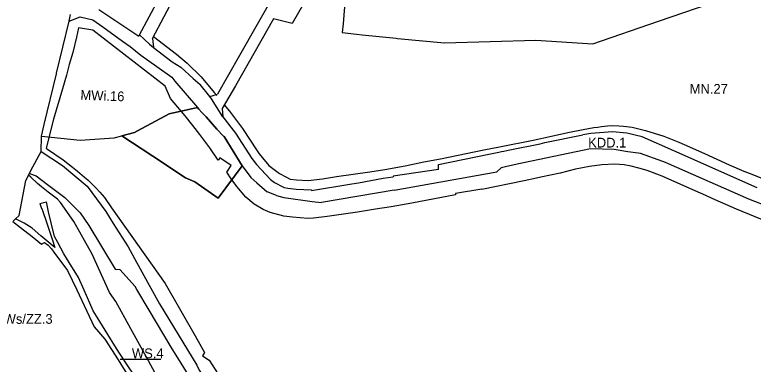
# Model space of a CAD drawing. Extents: x 7418991 to 7423142, y 5547704 to 5549547.
# Drawn here: x 7419654.4 to 7420035, y 5548816.8 to 5548996.8 of the extents above; entities that cross this region are included whole.
import ezdxf

# ---------------------------------------------------------------- set-up
doc = ezdxf.new("R2010")
doc.units = 0
for name, color, linetype in [('LIN_Linia Zabudowy Nieprzekraczalna', 7, 'Continuous'), ('LIN_linie_rozgraniczajace', 7, 'Continuous'), ('strefa_lokalizacji_usług', 7, 'Continuous'), ('TXT_Oznaczenia_przeznaczen', 7, 'Continuous')]:
    doc.layers.add(name, color=color, linetype=linetype)

msp = doc.modelspace()

# ---------------------------------------------------------------- linework, layer by layer
at = {"layer": 'LIN_Linia Zabudowy Nieprzekraczalna'}
for points in [[(7420045.62, 5548888.77), (7420026.39, 5548896.72), (7420015.43, 5548901.52), (7420008.94, 5548904.39), (7420003.92, 5548906.66), (7419988, 5548913.69), (7419980.27, 5548916.56), (7419976.07, 5548917.8), (7419972.03, 5548918.84), (7419968.54, 5548919.54), (7419963.69, 5548919.91), (7419956.87, 5548919.49), (7419950.58, 5548918.56), (7419943.4, 5548917.34), (7419935.48, 5548915.29), (7419925.44, 5548913.15), (7419923.24, 5548912.68), (7419916.91, 5548911.22), (7419895.09, 5548906.86), (7419895.06, 5548907.05), (7419881.49, 5548904.66), (7419881.58, 5548904.11), (7419859.09, 5548899.81), (7419848.41, 5548897.83), (7419840.39, 5548896.59), (7419830.96, 5548895.21), (7419815.4, 5548892.89), (7419808.38, 5548892), (7419805.4, 5548891.83), (7419797.49, 5548892.47), (7419793.15, 5548893.14), (7419786.02, 5548894.87), (7419782.45, 5548896.57), (7419777.79, 5548899.26), (7419773.51, 5548902.84), (7419768.81, 5548908.36), (7419766.01, 5548912.27), (7419763.62, 5548915.72), (7419765.86, 5548919.12), (7419760.14, 5548923.1), (7419759.33, 5548921.95), (7419759.29, 5548921.98), (7419754.95, 5548928.24), (7419749.76, 5548935.12), (7419746.24, 5548939.68), (7419742.23, 5548944.65), (7419734.66, 5548953.71), (7419731.95, 5548960.05), (7419694.59, 5548988.84), (7419687.31, 5548990.06), (7419686.16, 5548985.29), (7419684.29, 5548977.28), (7419682.52, 5548971.19), (7419681.01, 5548965.64), (7419679.03, 5548958.69), (7419674.4, 5548943.06), (7419670.62, 5548928.04), (7419670.7, 5548927.96), (7419671.2, 5548927.57), (7419679.33, 5548922.01), (7419684.19, 5548918.31), (7419686.79, 5548916.22), (7419690.4, 5548913.21), (7419691.98, 5548911.75), (7419693.63, 5548910.18), (7419695.35, 5548908.47), (7419696.33, 5548907.45), (7419698.16, 5548905.4), (7419700.63, 5548902.67), (7419704.33, 5548897.43), (7419731.96, 5548858.42), (7419747.34, 5548831.4), (7419752.24, 5548822.89), (7419751.11, 5548821.1), (7419754.53, 5548818.94), (7419759.18, 5548811.75)], [(7419725.91, 5548985.58), (7419737.67, 5548976.51), (7419743.17, 5548971.79)], [(7419743.17, 5548971.79), (7419750.43, 5548964.74), (7419757.23, 5548956.69), (7419758.46, 5548955.22)], [(7419762.4, 5548950.44), (7419765.06, 5548947.09), (7419771.7, 5548938.18), (7419779.3, 5548926.72), (7419780.44, 5548925.12), (7419785.42, 5548919.23), (7419790.8, 5548915.06), (7419794.11, 5548913.27), (7419796.36, 5548912.2), (7419799.55, 5548911.74), (7419805.62, 5548911.39), (7419813, 5548912.24), (7419820.13, 5548913.45)], [(7419873.78, 5548922.58), (7419896.06, 5548927.14), (7419904.24, 5548928.72), (7419921.52, 5548932.23), (7419931.02, 5548934.23), (7419939.39, 5548936.21), (7419947.36, 5548937.77), (7419952.81, 5548938.69), (7419954.96, 5548938.94), (7419956.77, 5548939.21), (7419959.8, 5548939.5), (7419962.45, 5548939.68), (7419965.76, 5548939.58), (7419968.18, 5548939.44), (7419972.58, 5548938.87), (7419979.54, 5548937.23), (7419988.95, 5548934.19), (7419996.58, 5548931.17), (7419999.41, 5548929.93), (7420009.83, 5548925.29), (7420016.16, 5548922.39), (7420022.61, 5548919.58)], [(7419820.13, 5548913.45), (7419837.44, 5548915.95), (7419845.12, 5548917.12), (7419855.52, 5548919.03), (7419865.27, 5548921), (7419873.78, 5548922.58)], [(7420022.61, 5548919.58), (7420030.2, 5548916.29), (7420032.93, 5548915.22), (7420038.5, 5548912.93), (7420052.44, 5548907.31), (7420057.96, 5548905.38), (7420062.32, 5548904.19), (7420064.15, 5548903.97), (7420069.56, 5548904.31), (7420075.9, 5548905.75), (7420086.49, 5548909.16)]]:
    msp.add_lwpolyline(points, dxfattribs=at)
at = {"layer": 'LIN_linie_rozgraniczajace'}
for p, q in [((7419725.38, 5548984.58), (7419725.97, 5548979.97)), ((7419735.52, 5548972.51), (7419739.93, 5548969.85)), ((7419739.93, 5548969.85), (7419746.39, 5548964.02)), ((7419746.39, 5548964.02), (7419749.9, 5548960.84)), ((7419754.93, 5548954.62), (7419758.81, 5548955.82)), ((7419990.6, 5548920.38), (7419991.12, 5548920.19)), ((7419991.12, 5548920.19), (7420032.47, 5548901.95)), ((7419662.65, 5548913.2), (7419661.56, 5548914.26)), ((7419666.1, 5548909.82), (7419662.65, 5548913.2)), ((7419668.11, 5548908.18), (7419666.1, 5548909.82)), ((7419671.66, 5548905.5), (7419668.11, 5548908.18)), ((7419676.37, 5548901.9), (7419671.66, 5548905.5)), ((7419789.25, 5548903.79), (7419784.44, 5548905.62)), ((7419849.87, 5548906.38), (7419812.41, 5548900.09)), ((7419677.9, 5548900.03), (7419676.37, 5548901.9)), ((7420032.47, 5548901.95), (7420048.13, 5548895.81)), ((7419667.24, 5548899.65), (7419670.74, 5548900.41)), ((7419684.78, 5548890.29), (7419677.9, 5548900.03)), ((7419694.25, 5548873.48), (7419684.78, 5548890.29)), ((7419703.22, 5548853.7), (7419694.25, 5548873.48)), ((7419706.53, 5548849.07), (7419703.22, 5548853.7)), ((7419714.22, 5548835.12), (7419706.53, 5548849.07)), ((7419722.21, 5548820.53), (7419714.22, 5548835.12)), ((7419727.78, 5548810.3), (7419722.21, 5548820.53))]:
    msp.add_line(p, q, dxfattribs=at)
for points in [[(7419725.38, 5548984.58), (7419743.43, 5549018.66), (7419752.66, 5549036.47), (7419758.51, 5549047.68), (7419761.28, 5549053.01), (7419770.56, 5549070.48), (7419778.22, 5549085.19)], [(7419826.52, 5549029.75), (7419823.65, 5548992.09), (7419823.17, 5548987.62), (7419830.59, 5548986.7), (7419833.39, 5548986.35), (7419850.9, 5548984.69), (7419851.58, 5548984.63), (7419875.92, 5548982.32), (7419922.96, 5548983.61), (7419952.37, 5548981.75), (7419986.14, 5548993.43), (7420032.36, 5549009.41)], [(7419697.79, 5548999.42), (7419718.4, 5548985.81), (7419718.73, 5548986.43), (7419738.68, 5549023.68)], [(7419791.76, 5549013.94), (7419788.37, 5549007.95), (7419770.15, 5548975.79), (7419758.81, 5548955.82)], [(7419791.76, 5549013.94), (7419803.14, 5549002.33), (7419797.44, 5548992.29), (7419787.73, 5548994.7), (7419768.08, 5548960.17), (7419761.25, 5548948.48), (7419761.68, 5548944.15)], [(7419653.46, 5548890.27), (7419654.85, 5548891.62), (7419656.7, 5548893.4), (7419660.1, 5548911.48), (7419662, 5548915.09), (7419662.74, 5548916.5), (7419662.74, 5548916.5), (7419667.94, 5548926.38), (7419668.15, 5548934.32), (7419669.59, 5548940.3), (7419675.86, 5548966.38), (7419675.96, 5548966.76), (7419682.36, 5548993.41), (7419683.19, 5548996.88)], [(7419682.36, 5548993.41), (7419688.03, 5548995.64), (7419694.55, 5548994.21), (7419699.8, 5548990.55), (7419709.84, 5548983.14), (7419713.81, 5548980.38), (7419719.44, 5548975.99), (7419727.55, 5548970.09), (7419735.43, 5548964.61), (7419736.92, 5548962.59), (7419748.5, 5548949.1), (7419748.62, 5548948.95), (7419749.34, 5548948.12), (7419750.88, 5548946.41), (7419751.71, 5548945.5), (7419752.97, 5548944.17), (7419758.62, 5548937.91), (7419761.93, 5548934.3), (7419762.27, 5548934.08), (7419771.53, 5548919.05), (7419776.03, 5548912.93), (7419779.09, 5548910.27), (7419784.44, 5548905.62)], [(7419718.73, 5548986.43), (7419723.83, 5548981.65), (7419725.97, 5548979.97), (7419735.52, 5548972.51)], [(7419761.68, 5548944.15), (7419755.82, 5548953.51), (7419754.93, 5548954.62), (7419749.9, 5548960.84)], [(7419668.15, 5548934.32), (7419688.08, 5548932.16), (7419705.57, 5548933.33), (7419709.56, 5548934.39), (7419716.19, 5548936.16), (7419717.72, 5548936.97), (7419734.03, 5548945.69), (7419748.5, 5548949.1)], [(7419761.68, 5548944.15), (7419768.13, 5548935.77), (7419776.66, 5548922.74), (7419779.02, 5548919.74), (7419786.2, 5548911.97), (7419788.18, 5548910.46), (7419792.82, 5548907.99), (7419793.17, 5548907.89), (7419795.12, 5548907.54), (7419799.45, 5548907.05), (7419807.37, 5548906.58), (7419807.37, 5548906.35), (7419828.18, 5548909.69), (7419831.49, 5548910.22), (7419844.28, 5548912.63), (7419849.35, 5548913.38), (7419849.47, 5548913.4)], [(7420037, 5548907.69), (7419994.04, 5548926.74), (7419977.79, 5548933.93), (7419969.89, 5548935.8), (7419962.51, 5548936.47), (7419951.22, 5548935.66), (7419947.24, 5548934.87)], [(7419872.74, 5548917.1), (7419872.82, 5548919.71), (7419898.78, 5548924.96), (7419903.93, 5548926.06), (7419905.22, 5548926.29), (7419906.38, 5548926.6), (7419909.57, 5548927.22), (7419925.24, 5548930.33), (7419927.54, 5548930.93), (7419947.24, 5548934.87)], [(7419951.18, 5548927.74), (7419913.39, 5548919.84), (7419905.01, 5548917.96)], [(7419990.6, 5548920.38), (7419988.32, 5548921.21), (7419976.92, 5548925.27), (7419975.76, 5548925.49), (7419970.36, 5548926.25), (7419963.3, 5548927.37), (7419951.18, 5548927.74)], [(7419667.94, 5548926.38), (7419678.93, 5548919.18), (7419691.77, 5548908.48), (7419701.28, 5548895.49), (7419705.16, 5548889.33), (7419712.83, 5548877.28), (7419717.15, 5548869.39)], [(7419872.74, 5548917.1), (7419849.48, 5548913.62), (7419849.47, 5548913.4)], [(7419849.87, 5548906.38), (7419902.77, 5548915.97), (7419905.01, 5548917.96)], [(7419662, 5548915.09), (7419665.42, 5548913.81), (7419671.33, 5548909.42), (7419680.14, 5548902.73), (7419681.09, 5548901.82), (7419684.61, 5548898.28), (7419688.12, 5548894.73), (7419692.62, 5548888.25), (7419706.09, 5548865.84)], [(7419789.25, 5548903.79), (7419793.11, 5548902.75), (7419807.72, 5548900.56), (7419812.41, 5548900.09)], [(7419667.24, 5548899.65), (7419668.18, 5548897), (7419668.4, 5548897.05), (7419671.03, 5548888.94), (7419672.57, 5548884.31), (7419673.72, 5548881.14), (7419675.03, 5548876.93)], [(7419674.86, 5548882.62), (7419673.14, 5548889.58), (7419671.81, 5548895.22), (7419670.74, 5548900.41)], [(7419653.46, 5548890.27), (7419657.38, 5548887.2), (7419663.34, 5548882.63), (7419668.24, 5548878.71), (7419669.69, 5548879.5), (7419671.68, 5548878.12), (7419673.38, 5548876.24), (7419674.6, 5548874.55), (7419681.66, 5548865.01)], [(7419675.03, 5548876.93), (7419667.9, 5548882.94), (7419663.38, 5548886.82), (7419659.21, 5548889.52), (7419654.85, 5548891.62)], [(7419725.26, 5548796.05), (7419722.48, 5548801.11), (7419720.88, 5548803.83), (7419720.03, 5548805.19), (7419717.65, 5548808.74), (7419713.44, 5548815.02), (7419708.31, 5548822.59), (7419706.01, 5548826.24), (7419702.41, 5548832.08), (7419698.25, 5548838.79), (7419694.79, 5548844.36), (7419690.11, 5548854.93), (7419687.2, 5548861.42), (7419682.37, 5548869.22), (7419679.61, 5548873.71), (7419676.54, 5548879.52), (7419674.86, 5548882.62)], [(7419717.15, 5548869.39), (7419723.59, 5548857.61), (7419729.07, 5548847.98), (7419748.22, 5548816.34), (7419749.51, 5548813.77), (7419753.32, 5548807.54), (7419755.8, 5548803.39), (7419756.6, 5548802), (7419763.76, 5548793.63), (7419766.31, 5548790.65), (7419768.6, 5548788.05), (7419776.43, 5548778.71), (7419777.63, 5548777.29), (7419780.05, 5548774.53), (7419784.81, 5548768.75)], [(7419681.66, 5548865.01), (7419686.39, 5548855.19), (7419695.39, 5548836.11), (7419700.86, 5548829.76), (7419707.66, 5548819.11), (7419711.37, 5548813.25), (7419715.25, 5548807.22), (7419719.45, 5548799.99), (7419721.69, 5548795.94)], [(7419706.09, 5548865.84), (7419708.61, 5548865.61), (7419716.43, 5548856.83)], [(7419723.7, 5548844.72), (7419717.34, 5548855.33), (7419716.43, 5548856.83)], [(7419773.52, 5548771.86), (7419766.66, 5548779.77), (7419748.11, 5548804.68), (7419735.05, 5548825.68), (7419723.7, 5548844.72)]]:
    msp.add_lwpolyline(points, dxfattribs=at)
at = {"layer": 'strefa_lokalizacji_usług'}
for p, q in [((7419734.03, 5548945.69), (7419748.5, 5548949.1)), ((7419748.5, 5548949.1), (7419734.03, 5548945.69)), ((7419748.5, 5548949.1), (7419748.62, 5548948.95)), ((7419748.62, 5548948.95), (7419748.5, 5548949.1)), ((7419748.62, 5548948.95), (7419749.34, 5548948.12)), ((7419749.34, 5548948.12), (7419748.62, 5548948.95)), ((7419749.34, 5548948.12), (7419750.88, 5548946.41)), ((7419750.88, 5548946.41), (7419749.34, 5548948.12)), ((7419717.72, 5548936.97), (7419734.03, 5548945.69)), ((7419734.03, 5548945.69), (7419717.72, 5548936.97)), ((7419750.88, 5548946.41), (7419751.71, 5548945.5)), ((7419751.71, 5548945.5), (7419750.88, 5548946.41)), ((7419751.71, 5548945.5), (7419752.97, 5548944.17)), ((7419752.97, 5548944.17), (7419751.71, 5548945.5)), ((7419752.97, 5548944.17), (7419758.62, 5548937.91)), ((7419758.62, 5548937.91), (7419752.97, 5548944.17)), ((7419709.56, 5548934.39), (7419716.19, 5548936.16)), ((7419716.19, 5548936.16), (7419709.56, 5548934.39)), ((7419716.19, 5548936.16), (7419717.72, 5548936.97)), ((7419717.72, 5548936.97), (7419716.19, 5548936.16)), ((7419758.62, 5548937.91), (7419761.93, 5548934.3)), ((7419761.93, 5548934.3), (7419758.62, 5548937.91)), ((7419725.63, 5548923.99), (7419709.56, 5548934.39)), ((7419709.56, 5548934.39), (7419725.63, 5548923.99)), ((7419761.93, 5548934.3), (7419762.27, 5548934.08)), ((7419762.27, 5548934.08), (7419761.93, 5548934.3)), ((7419762.27, 5548934.08), (7419771.53, 5548919.05)), ((7419771.53, 5548919.05), (7419762.27, 5548934.08)), ((7419742.41, 5548912.72), (7419725.63, 5548923.99)), ((7419725.63, 5548923.99), (7419742.41, 5548912.72)), ((7419771.53, 5548919.05), (7419759.27, 5548902.35)), ((7419759.27, 5548902.35), (7419771.53, 5548919.05)), ((7419747.27, 5548910.72), (7419742.41, 5548912.72)), ((7419742.41, 5548912.72), (7419747.27, 5548910.72)), ((7419759.27, 5548902.35), (7419747.27, 5548910.72)), ((7419747.27, 5548910.72), (7419759.27, 5548902.35))]:
    msp.add_line(p, q, dxfattribs=at)
at = {"layer": 'TXT_Oznaczenia_przeznaczen'}
msp.add_line((7419708.77, 5548819.42), (7419729.72, 5548819.42), dxfattribs=at)

# ---------------------------------------------------------------- texts
for s, p in [('MN.27', (7420002.22, 5548956.12)), ('KDD.1', (7419949.89, 5548928.42)), ('ZWs/ZZ.3', (7419644.58, 5548837.65)), ('WS.4', (7419714.77, 5548819.95))]:
    msp.add_text(s, height=5, dxfattribs=at).set_placement(p)
msp.add_text('MWi.16', height=5, rotation=357.9964, dxfattribs=at).set_placement((7419688.18, 5548952.99))

doc.saveas('drawing.dxf')
